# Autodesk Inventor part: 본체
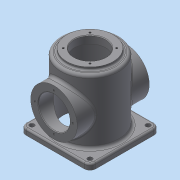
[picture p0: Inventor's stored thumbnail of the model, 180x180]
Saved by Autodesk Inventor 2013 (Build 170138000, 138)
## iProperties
Created: 2015-10
Part Number: 본체
Material: 일반
Document SubType Name: Modeling
Designer: dgall
Density: 1 g/cm^3
Author: dgall
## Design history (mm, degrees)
sketch "스케치1"
  geometry: L1 (-60, 60)-(60, 60); L2 (60, 60)-(60, -60); L3 (60, -60)-(-60, -60); L4 (-60, -60)-(-60, 60); L5 (-60, 60)-(60, -60); L6 (60, 60)-(-60, -60); C1 r 4 at (-50, 50); C2 r 4 at (50, 50); C3 r 4 at (50, -50); C4 r 4 at (-50, -50); 1 further point
  constraints: 12 end point, 4 centre point, 3 equal radius, 2 horizontal alignment, 2 midpoint, 2 parallel, 2 perpendicular, 2 vertical alignment, 1 horizontal
  dimensions: "d0" = 120 distance of L2.end L3.end; "d1" = 8 diameter of C1; "d2" = 100 distance of C2.centre C1.centre; "d3" = 50 horizontal distance of point (0, 0) C1.centre; "d4" = 100 distance of C3.centre C2.centre; "d5" = 50 horizontal distance of point (0, 0) C3.centre
extrude "돌출1" new body sketch "스케치1" distance "d6" = 10; taper "d7" = 0 deg
sketch "스케치2"
  geometry: C1 r 50 at (0, 0); C2 r 27 at (0, 0); 1 further point
  constraints: 2 centre point, 2 coincident
  dimensions: "d8" = 100 diameter of C1; "d9" = 54 diameter of C2
extrude "돌출2" join sketch "스케치2" distance "d10" = 115; taper "d11" = 0 deg
sketch "스케치4"
  geometry: C1 r 45 at (0, 0); 1 further point
  constraints: 1 centre point, 1 coincident
  dimensions: "d25" = 90 diameter of C1
extrude "돌출4" cut sketch "스케치4" distance "d26" = 112; taper "d27" = 0 deg
sketch "스케치5"
  geometry: C1 r 50 at (0, 0) reference; C2 r 50 at (0, 0); C3 r 40 at (0, 0)
  constraints: 2 centre point, 2 coincident
  dimensions: "d28" = 100 diameter of C2; "d29" = 80 diameter of C3
extrude "돌출5" cut sketch "스케치5" distance "d30" = 5; taper "d31" = 0 deg
fillet "모깎기1" dims "d32" = 10
sketch "스케치6"
  geometry: C1 r 4 at (-50, 50); C2 r 4 at (50, 50); C3 r 4 at (50, -50); C4 r 4 at (-50, -50); A1 r 10 centre (-50, 50) between (-50, 60) and (-60, 50) reference; A2 r 10 centre (-50, -50) between (-60, -50) and (-50, -60) reference; A3 r 10 centre (50, -50) between (50, -60) and (60, -50) reference; A4 r 10 centre (50, 50) between (60, 50) and (50, 60) reference
  constraints: 4 centre point, 4 coincident, 1 equal radius
  dimensions: "d33" = 8 diameter of C1; "d34" = 8 diameter of C3; "d35" = 8 diameter of C4
hole "구멍2" sketch "스케치6" at (-50, -50), (50, 50), (50, -50), (-50, 50) diameter "d36" = 8; stored, may be unused: countersink angle "d40" = 90 deg, drill point angle "d42" = 118 deg; dims "d37" = 6, "d38" = 4, "d39" = 2, "d41" = 8
fillet "모깎기2" dims "d43" = 5
sketch "스케치7"
  geometry: L1 (0, 100)-(0, 0) reference; 3 further points
  constraints: 1 horizontal alignment, 1 midpoint, 1 other
  dimensions: "d44" = 70 distance of point (0, 50) point (-70, 50)
feature "엠보싱1" sketch "스케치7" dims "d0" = 120, "d27" = 0, "d45" = 0.5, "d46" = 0
hole "구멍3" diameter "d52" = 54; stored, may be unused: countersink angle "d56" = 90 deg, drill point angle "d58" = 118 deg; dims "d50" = 10, "d51" = 10, "d53" = 6, "d54" = 4, "d55" = 2, "d57" = 8
sketch "스케치9"
  geometry: L1 (0, 0)-(-32.5, 0); L2 (0, 0)-(-22.981, -22.981); C1 r 40 at (0, 0) reference; A1 r 32.5 centre (0, 0) between (-32.5, 0) and (-22.981, -22.981); 1 further point
  constraints: 4 end point, 2 coincident, 2 point on circle, 1 centre point, 1 horizontal
  dimensions: "d60" = 65 diameter of A1; "d61" = 45 deg angle of L1 L2
hole "구멍4" sketch "스케치9" at (-22.981, -22.981) diameter "d63" = 3.242; stored, may be unused: countersink angle "d67" = 90 deg, drill point angle "d69" = 118 deg; dims "d64" = 8, "d65" = 4, "d66" = 2, "d68" = 10
sketch "스케치8"
  geometry: C1 r 40 at (0, 60); C2 r 27 at (0, 60); 1 further point
  constraints: 2 centre point, 1 concentric, 1 vertical alignment
  dimensions: "d47" = 80 diameter of C1; "d48" = 54 diameter of C2; "d49" = 60 distance of point (0, 0) C1.centre
extrude "돌출6" join sketch "스케치8" stored distance "d73" = 124; taper "d74" = 0 deg
extrude "돌출7" cut sketch "스케치8" stored distance "d75" = 124; taper "d76" = 0 deg
fillet "모깎기4" dims "d77" = 5
sketch "스케치10"
  geometry: L1 (0, 0)-(0, -32.5); C1 r 40 at (0, 0) reference; 2 further points
  constraints: 2 end point, 1 coincident, 1 vertical
  dimensions: "d78" = 32.5 distance of L1.start L1.end
hole "구멍5" sketch "스케치10" at (0, -32.5) diameter "d79" = 3.242; stored, may be unused: countersink angle "d83" = 90 deg, drill point angle "d85" = 118 deg; dims "d80" = 8, "d81" = 4, "d82" = 2, "d84" = 10
sketch "스케치11"
  geometry: L1 (0, 0)-(0, 32.5); C1 r 40 at (0, 0) reference; 2 further points
  constraints: 2 end point, 1 coincident, 1 vertical
  dimensions: "d89" = 32.5 distance of L1.start L1.end
hole "구멍6" sketch "스케치11" at (0, 32.5) diameter "d90" = 3.242; stored, may be unused: countersink angle "d94" = 90 deg, drill point angle "d96" = 118 deg; dims "d91" = 8, "d92" = 4, "d93" = 2, "d95" = 10
extrude "돌출8" cut sketch "스케치4" distance "d100" = 112; taper "d101" = 0 deg
fillet "모깎기3" dims "d59" = 3
chamfer "모따기1" distance "d102" = 1; stored, may be unused: second distance "d103" = 2, angle "d104" = 45 deg
chamfer "모따기2" distance "d105" = 1; stored, may be unused: second distance "d106" = 2, angle "d107" = 45 deg
chamfer "모따기3" distance "d108" = 1; stored, may be unused: second distance "d109" = 2, angle "d110" = 45 deg
chamfer "모따기4" distance "d111" = 3; stored, may be unused: second distance "d112" = 2, angle "d113" = 45 deg
fillet "모깎기5" dims "d114" = 3
node "솔리드1"
pattern_circular "원형 패턴1" dims angle "d71" = 360 deg
pattern_circular "원형 패턴2" dims angle "d87" = 360 deg
pattern_circular "원형 패턴3" dims angle "d98" = 360 deg
